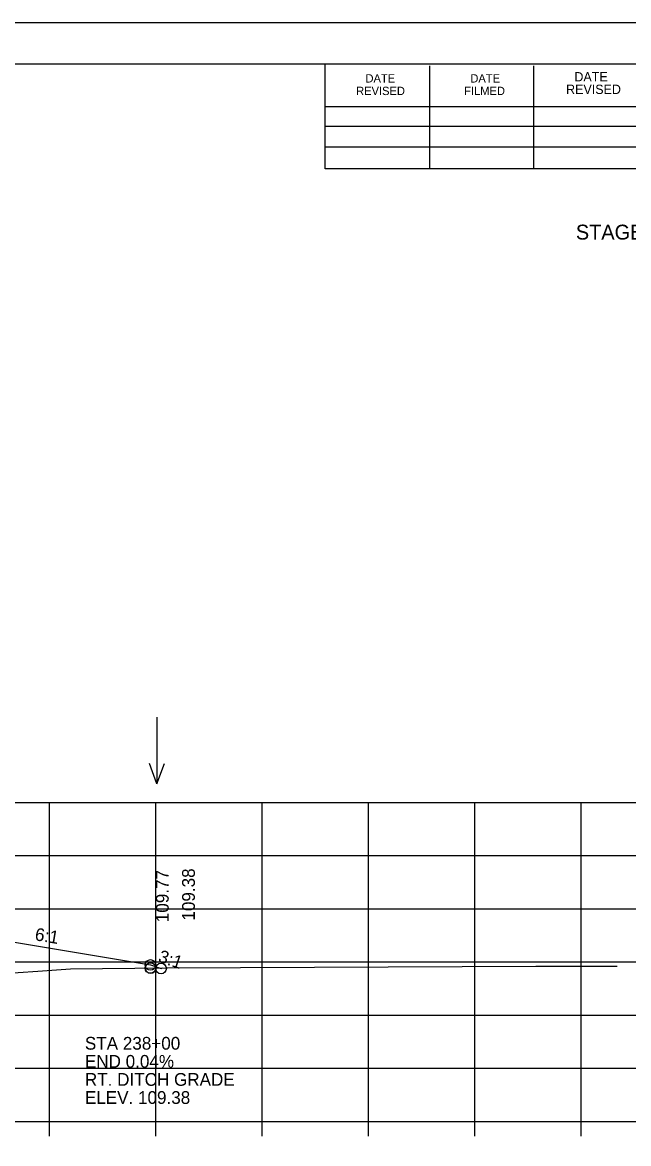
# Model space of a CAD drawing. Extents: x 1175611 to 1176402, y -433344 to -416213.
# Drawn here: x 1175828.4 to 1175885.4, y -422355.4 to -422250 of the extents above; entities that cross this region are included whole.
import ezdxf

# ---------------------------------------------------------------- set-up
doc = ezdxf.new("R2010")
doc.units = 0
for name, color, linetype in [('Default', 7, 'Continuous'), ('R_Axis', 7, 'Continuous'), ('R_Border', 7, 'Continuous'), ('R_Exist Surface', 7, 'Continuous'), ('R_Fin Surface', 7, 'Continuous'), ('R_Grid', 7, 'Continuous'), ('R_No Plot', 7, 'Continuous'), ('R_Water Annot', 7, 'Continuous'), ('R_Xsect Elev', 7, 'Continuous'), ('R_Xsect Slope', 7, 'Continuous')]:
    doc.layers.add(name, color=color, linetype=linetype)

msp = doc.modelspace()

# ---------------------------------------------------------------- linework, layer by layer
at = {"layer": 'R_Axis'}
for p, q in [((1175640.97, -422353.31), (1175920.97, -422353.31)), ((1175830.97, -422354.71), (1175830.97, -422353.31)), ((1175840.97, -422354.71), (1175840.97, -422353.31)), ((1175850.97, -422354.71), (1175850.97, -422353.31)), ((1175860.97, -422354.71), (1175860.97, -422353.31)), ((1175870.97, -422354.71), (1175870.97, -422353.31)), ((1175880.97, -422354.71), (1175880.97, -422353.31))]:
    msp.add_line(p, q, dxfattribs=at)
at = {"layer": 'R_Border'}
for p, q in [((1175622.97, -422253.85), (1175939.15, -422253.85)), ((1175856.89, -422263.73), (1175856.89, -422253.85)), ((1175866.75, -422263.73), (1175866.75, -422254.05)), ((1175876.51, -422263.73), (1175876.51, -422254.05)), ((1175856.89, -422257.87), (1175896.05, -422257.87)), ((1175856.89, -422259.73), (1175896.05, -422259.73)), ((1175856.89, -422263.73), (1175856.89, -422261.67)), ((1175856.89, -422261.67), (1175896.05, -422261.67)), ((1175939.15, -422263.73), (1175856.89, -422263.73))]:
    msp.add_line(p, q, dxfattribs=at)
at = {"layer": 'R_Exist Surface'}
msp.add_lwpolyline([(1175816.9, -422340.07), (1175829.88, -422339.19), (1175832.97, -422338.97), (1175842.03, -422338.88), (1175876.71, -422338.71), (1175883.81, -422338.72), (1175884.34, -422338.72)], dxfattribs=at)
at = {"layer": 'R_Fin Surface'}
msp.add_lwpolyline([(1175719.3, -422339.32), (1175721.47, -422338.6), (1175735.2, -422336.31), (1175743.47, -422334.93), (1175749.47, -422334.69), (1175751.47, -422334.65), (1175780.97, -422334.06), (1175810.47, -422334.65), (1175812.47, -422334.69), (1175818.47, -422334.93), (1175826.75, -422336.31), (1175840.47, -422338.6), (1175841.47, -422338.93), (1175841.62, -422338.88)], dxfattribs=at)
at = {"layer": 'R_Grid'}
for p, q in [((1175640.97, -422323.31), (1175920.97, -422323.31)), ((1175640.97, -422323.31), (1175920.97, -422323.31)), ((1175830.97, -422353.31), (1175830.97, -422323.31)), ((1175830.97, -422353.31), (1175830.97, -422323.31)), ((1175840.97, -422353.31), (1175840.97, -422323.31)), ((1175840.97, -422353.31), (1175840.97, -422323.31)), ((1175850.97, -422353.31), (1175850.97, -422323.31)), ((1175850.97, -422353.31), (1175850.97, -422323.31)), ((1175860.97, -422353.31), (1175860.97, -422323.31)), ((1175860.97, -422353.31), (1175860.97, -422323.31)), ((1175870.97, -422353.31), (1175870.97, -422323.31)), ((1175870.97, -422353.31), (1175870.97, -422323.31)), ((1175880.97, -422353.31), (1175880.97, -422323.31)), ((1175880.97, -422353.31), (1175880.97, -422323.31)), ((1175640.97, -422328.31), (1175920.97, -422328.31)), ((1175640.97, -422328.31), (1175920.97, -422328.31)), ((1175640.97, -422333.31), (1175920.97, -422333.31)), ((1175640.97, -422333.31), (1175920.97, -422333.31)), ((1175640.97, -422338.31), (1175920.97, -422338.31)), ((1175640.97, -422338.31), (1175920.97, -422338.31)), ((1175640.97, -422343.31), (1175920.97, -422343.31)), ((1175640.97, -422343.31), (1175920.97, -422343.31)), ((1175640.97, -422348.31), (1175920.97, -422348.31)), ((1175640.97, -422348.31), (1175920.97, -422348.31)), ((1175640.97, -422353.31), (1175920.97, -422353.31)), ((1175640.97, -422353.31), (1175920.97, -422353.31))]:
    msp.add_line(p, q, dxfattribs=at)
at = {"layer": 'R_No Plot'}
msp.add_line((1175610.57, -422249.96), (1175943.91, -422249.96), dxfattribs=at)
msp.add_lwpolyline([(1175610.57, -422249.96), (1175943.91, -422249.96), (1175943.91, -422463.3), (1175610.57, -422463.3)], close=True, dxfattribs=at)
for centre in [(1175840.47, -422338.6), (1175840.47, -422338.89), (1175840.5, -422338.9), (1175840.5, -422338.9), (1175841.47, -422338.93), (1175841.47, -422338.93)]:
    msp.add_circle(centre, 0.5, dxfattribs=at)
at = {"layer": 'R_Water Annot'}
for p, q in [((1175841.08, -422315.29), (1175841.08, -422321.57)), ((1175841.08, -422321.57), (1175840.38, -422319.65)), ((1175841.08, -422321.57), (1175841.78, -422319.65))]:
    msp.add_line(p, q, dxfattribs=at)

# ---------------------------------------------------------------- texts
at = {"layer": 'Default'}
msp.add_text('STAGE 1     STAGE 2', height=1.4, dxfattribs=at).set_placement((1175880.47, -422270.38))
at = {"layer": 'R_Border'}
for s, height, p in [('DATE', 0.782, (1175860.69, -422255.61)), ('DATE', 0.782, (1175870.55, -422255.61)), ('DATE', 0.879, (1175880.33, -422255.51)), ('REVISED', 0.782, (1175859.81, -422256.79)), ('FILMED', 0.782, (1175869.97, -422256.79)), ('REVISED', 0.879, (1175879.55, -422256.69))]:
    msp.add_text(s, height=height, rotation=360, dxfattribs=at).set_placement(p)
at = {"layer": 'R_Water Annot'}
for s, p in [('STA 238+00', (1175834.31, -422346.57)), ('END 0.04%', (1175834.31, -422348.27)), ('RT. DITCH GRADE', (1175834.31, -422349.97)), ('ELEV. 109.38', (1175834.31, -422351.67))]:
    msp.add_text(s, height=1.2, dxfattribs=at).set_placement(p)
at = {"layer": 'R_Xsect Elev'}
for s, p in [('109.77', (1175842.19, -422334.58)), ('109.38', (1175844.65, -422334.43))]:
    msp.add_text(s, height=1.2, rotation=90, dxfattribs=at).set_placement(p)
at = {"layer": 'R_Xsect Slope'}
for s, rotation, p in [('6:1', 350.5377, (1175829.55, -422336.27)), ('3:1', 341.5651, (1175841.13, -422338.29))]:
    msp.add_text(s, height=1.2, rotation=rotation, dxfattribs=at).set_placement(p)

doc.saveas('drawing.dxf')
